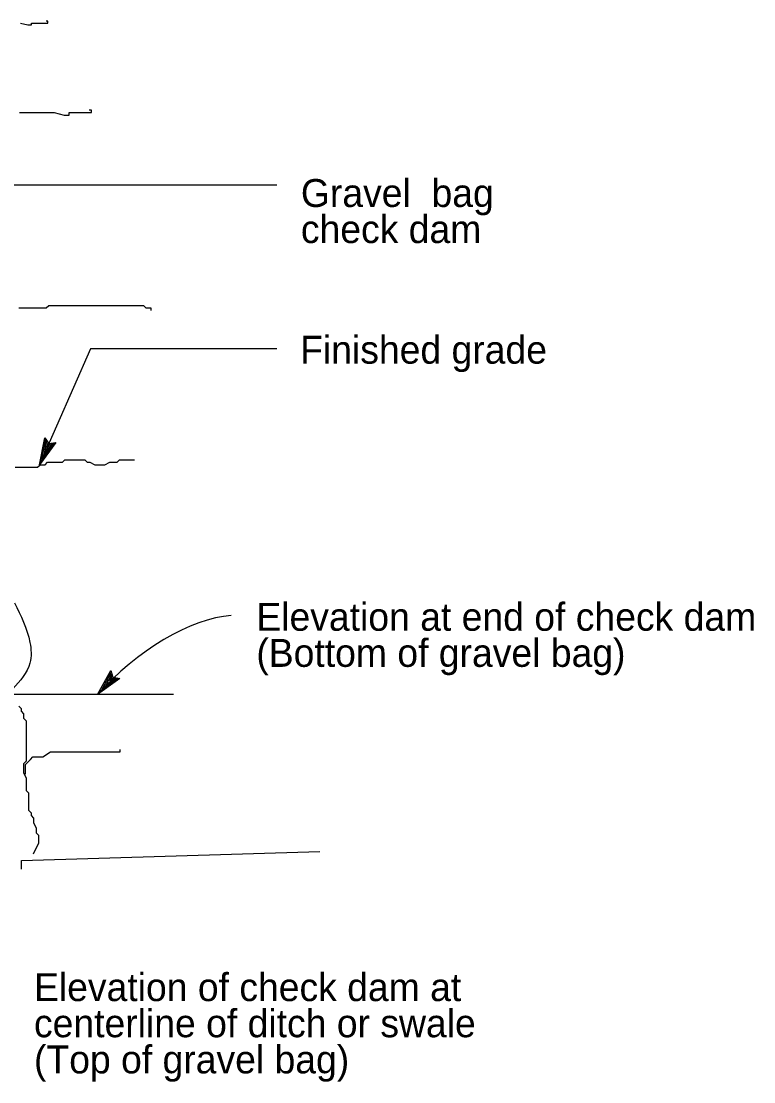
# Model space of a CAD drawing. Extents: x 6707415 to 6708768, y 1869893 to 1870831.
# Drawn here: x 6708608.7 to 6708766.2, y 1870157.2 to 1870385.2 of the extents above; entities that cross this region are included whole.
import ezdxf

# ---------------------------------------------------------------- set-up
doc = ezdxf.new("R2010")
doc.units = 0
for name, color, linetype in [('56 Stg 3 Anno', 7, 'Continuous'), ('57 Undefined', 7, 'Continuous'), ('60 Nongeo Data', 7, 'Continuous')]:
    doc.layers.add(name, color=color, linetype=linetype)

msp = doc.modelspace()

# ---------------------------------------------------------------- linework, layer by layer
at = {"layer": '56 Stg 3 Anno'}
for p, q in [((6708663.64, 1870350), (6708584.76, 1870350)), ((6708623.6, 1870314.81), (6708612.63, 1870289.9)), ((6708663.64, 1870314.81), (6708623.6, 1870314.81)), ((6708612.63, 1870289.9), (6708613.77, 1870295.68)), ((6708616.12, 1870294.65), (6708612.63, 1870289.9)), ((6708613.16, 1870291.12), (6708614, 1870295.34)), ((6708615.72, 1870294.6), (6708613.16, 1870291.11)), ((6708613.69, 1870292.33), (6708614.23, 1870295.05)), ((6708615.32, 1870294.53), (6708613.69, 1870292.33)), ((6708613.77, 1870295.68), (6708613.77, 1870295.68)), ((6708613.77, 1870295.68), (6708614.63, 1870294.47)), ((6708614.23, 1870293.54), (6708614.46, 1870294.7)), ((6708614.94, 1870294.51), (6708614.23, 1870293.54)), ((6708614.63, 1870294.47), (6708616.12, 1870294.65)), ((6708616.12, 1870294.65), (6708616.12, 1870294.65)), ((6708612.63, 1870289.9), (6708612.63, 1870289.9)), ((6708625.12, 1870240.47), (6708627.96, 1870245.64)), ((6708629.89, 1870243.95), (6708625.12, 1870240.47)), ((6708626, 1870241.47), (6708628.07, 1870245.24)), ((6708629.49, 1870244.02), (6708626, 1870241.46)), ((6708626.87, 1870242.46), (6708628.21, 1870244.9)), ((6708629.09, 1870244.08), (6708626.87, 1870242.46)), ((6708627.75, 1870243.46), (6708628.32, 1870244.5)), ((6708628.72, 1870244.17), (6708627.75, 1870243.46)), ((6708627.96, 1870245.64), (6708627.96, 1870245.64)), ((6708627.96, 1870245.64), (6708628.41, 1870244.22)), ((6708628.41, 1870244.22), (6708629.89, 1870243.95)), ((6708629.89, 1870243.95), (6708629.89, 1870243.95)), ((6708641.41, 1870240.47), (6708462.78, 1870240.47)), ((6708625.12, 1870240.47), (6708625.12, 1870240.47))]:
    msp.add_line(p, q, dxfattribs=at)
msp.add_ellipse((6708639.82, 1870237.37), major_axis=(-21.36, -17.68), ratio=0.450502, start_param=3.694848, end_param=5.056238, dxfattribs=at)
at = {"layer": '60 Nongeo Data'}
for points in [[(6708608.57, 1870384.85), (6708610.13, 1870384.47), (6708610.91, 1870384.47), (6708610.91, 1870384.85), (6708611.69, 1870384.86), (6708612.08, 1870384.85), (6708612.47, 1870384.86), (6708612.86, 1870384.86), (6708613.25, 1870384.86), (6708613.64, 1870384.85), (6708614.03, 1870384.86), (6708614.03, 1870384.86), (6708614.42, 1870384.85), (6708614.42, 1870385.25), (6708614.03, 1870385.24)], [(6708608.29, 1870365.62), (6708608.83, 1870365.62), (6708609.36, 1870365.62), (6708609.9, 1870365.62), (6708610.43, 1870365.62), (6708610.97, 1870365.62), (6708611.5, 1870365.62), (6708612.04, 1870365.62), (6708613.11, 1870365.62), (6708614.18, 1870365.62), (6708615.25, 1870365.62), (6708615.79, 1870365.62), (6708617.93, 1870365.08), (6708619, 1870365.08), (6708619, 1870365.62), (6708620.07, 1870365.62), (6708620.6, 1870365.62), (6708621.14, 1870365.62), (6708621.67, 1870365.62), (6708622.21, 1870365.62), (6708622.74, 1870365.62), (6708623.28, 1870365.62), (6708623.28, 1870365.62), (6708623.82, 1870365.62), (6708623.82, 1870366.15), (6708623.28, 1870366.15)], [(6708608.21, 1870323.6), (6708608.74, 1870323.6), (6708609.28, 1870323.6), (6708609.81, 1870323.6), (6708610.35, 1870323.6), (6708610.88, 1870323.6), (6708611.42, 1870323.6), (6708611.95, 1870323.6), (6708612.49, 1870323.6), (6708613.02, 1870323.6), (6708613.56, 1870323.6), (6708614.09, 1870323.6), (6708614.63, 1870324.14), (6708615.17, 1870324.14), (6708616.24, 1870324.14), (6708617.31, 1870324.14), (6708617.84, 1870324.14), (6708618.91, 1870324.14), (6708620.52, 1870324.14), (6708621.59, 1870324.14), (6708622.12, 1870324.14), (6708623.19, 1870324.14), (6708623.73, 1870324.14), (6708624.26, 1870324.14), (6708624.8, 1870324.14), (6708625.33, 1870324.14), (6708625.87, 1870324.14), (6708626.41, 1870324.14), (6708626.94, 1870324.14), (6708628.55, 1870324.14), (6708629.08, 1870324.14), (6708631.22, 1870324.14), (6708631.76, 1870324.14), (6708632.83, 1870324.14), (6708633.36, 1870324.14), (6708633.9, 1870324.14), (6708634.43, 1870324.14), (6708634.97, 1870324.14), (6708635.5, 1870323.6), (6708636.04, 1870323.6), (6708636.04, 1870323.6), (6708636.58, 1870323.6), (6708636.58, 1870323.07)], [(6708607.38, 1870289.36), (6708608.99, 1870289.36), (6708609.52, 1870289.36), (6708610.06, 1870289.36), (6708611.13, 1870289.36), (6708611.67, 1870289.36), (6708612.2, 1870289.36), (6708612.74, 1870289.9), (6708613.27, 1870289.9), (6708613.81, 1870289.9), (6708614.34, 1870290.43), (6708615.41, 1870290.43), (6708616.48, 1870290.43), (6708617.55, 1870290.43), (6708618.09, 1870290.97), (6708619.16, 1870290.97), (6708619.69, 1870290.97), (6708620.77, 1870290.97), (6708621.84, 1870290.97), (6708622.37, 1870290.97), (6708622.91, 1870290.43), (6708623.44, 1870290.43), (6708624.51, 1870289.9), (6708625.05, 1870289.9), (6708625.58, 1870289.9), (6708626.65, 1870289.9), (6708627.72, 1870290.43), (6708628.26, 1870290.43), (6708629.33, 1870290.43), (6708629.86, 1870290.97), (6708630.4, 1870290.97), (6708630.93, 1870290.97), (6708632.01, 1870290.97), (6708632.54, 1870290.97), (6708633.08, 1870290.97), (6708633.08, 1870290.97)], [(6708611.32, 1870206.27), (6708612.48, 1870208.58), (6708612.48, 1870209.11), (6708612.48, 1870209.65), (6708612.48, 1870210.18), (6708611.95, 1870210.72), (6708611.95, 1870211.25), (6708611.95, 1870211.79), (6708611.41, 1870212.86), (6708611.41, 1870213.39), (6708611.41, 1870213.93), (6708610.88, 1870214.46), (6708610.88, 1870214.99), (6708610.34, 1870215.53), (6708610.34, 1870216.06), (6708610.34, 1870217.13), (6708610.34, 1870217.67), (6708610.34, 1870218.2), (6708610.34, 1870219.27), (6708609.81, 1870219.81), (6708609.81, 1870220.34), (6708609.81, 1870221.41), (6708609.81, 1870222.48), (6708609.27, 1870223.55), (6708609.27, 1870224.08), (6708609.27, 1870224.62), (6708609.27, 1870225.15), (6708609.27, 1870225.68), (6708609.81, 1870226.22), (6708609.81, 1870226.75), (6708609.81, 1870227.82), (6708609.81, 1870228.36), (6708609.81, 1870228.89), (6708609.81, 1870229.96), (6708609.81, 1870230.49), (6708609.81, 1870231.03), (6708609.81, 1870231.56), (6708609.81, 1870232.1), (6708609.81, 1870232.63), (6708609.81, 1870233.17), (6708609.81, 1870233.7), (6708609.81, 1870234.24), (6708609.81, 1870234.77), (6708609.27, 1870235.31), (6708609.27, 1870235.84), (6708609.27, 1870236.37), (6708608.74, 1870236.91), (6708608.74, 1870237.44), (6708608.2, 1870237.98)], [(6708609.6, 1870223.35), (6708609.6, 1870225.48), (6708610.67, 1870226.55), (6708611.21, 1870227.09), (6708612.81, 1870227.09), (6708613.35, 1870227.09), (6708614.96, 1870228.16), (6708615.49, 1870228.16), (6708616.56, 1870228.16), (6708617.1, 1870228.16), (6708618.17, 1870228.16), (6708618.7, 1870228.16), (6708619.24, 1870228.16), (6708619.77, 1870228.16), (6708620.31, 1870228.16), (6708621.38, 1870228.16), (6708622.45, 1870228.16), (6708623.52, 1870228.16), (6708624.59, 1870228.16), (6708625.13, 1870228.16), (6708626.73, 1870228.16), (6708627.27, 1870228.16), (6708628.34, 1870228.16), (6708628.87, 1870228.16), (6708629.41, 1870228.16), (6708629.94, 1870228.16), (6708629.94, 1870228.16), (6708629.94, 1870228.69)], [(6708608.72, 1870202.95), (6708608.79, 1870204.82), (6708672.92, 1870206.72)]]:
    msp.add_lwpolyline(points, dxfattribs=at)
msp.add_spline([(6708607.24, 1870260.19), (6708610.57, 1870251.69), (6708610.57, 1870247.25), (6708606.87, 1870241.71)], degree=3, dxfattribs=at)

# ---------------------------------------------------------------- texts
at = {"layer": '57 Undefined'}
for s, p in [('Gravel  bag', (6708668.83, 1870345.31)), ('check dam', (6708668.83, 1870337.55)), ('Finished grade', (6708668.67, 1870311.62)), ('Elevation at end of check dam', (6708659.25, 1870254.2)), ('(Bottom of gravel bag)', (6708659.25, 1870246.44)), ('Elevation of check dam at', (6708611.44, 1870174.58)), ('centerline of ditch or swale', (6708611.44, 1870166.81)), ('(Top of gravel bag)', (6708611.44, 1870159.04))]:
    msp.add_text(s, height=6, dxfattribs=at).set_placement(p)

doc.saveas('drawing.dxf')
